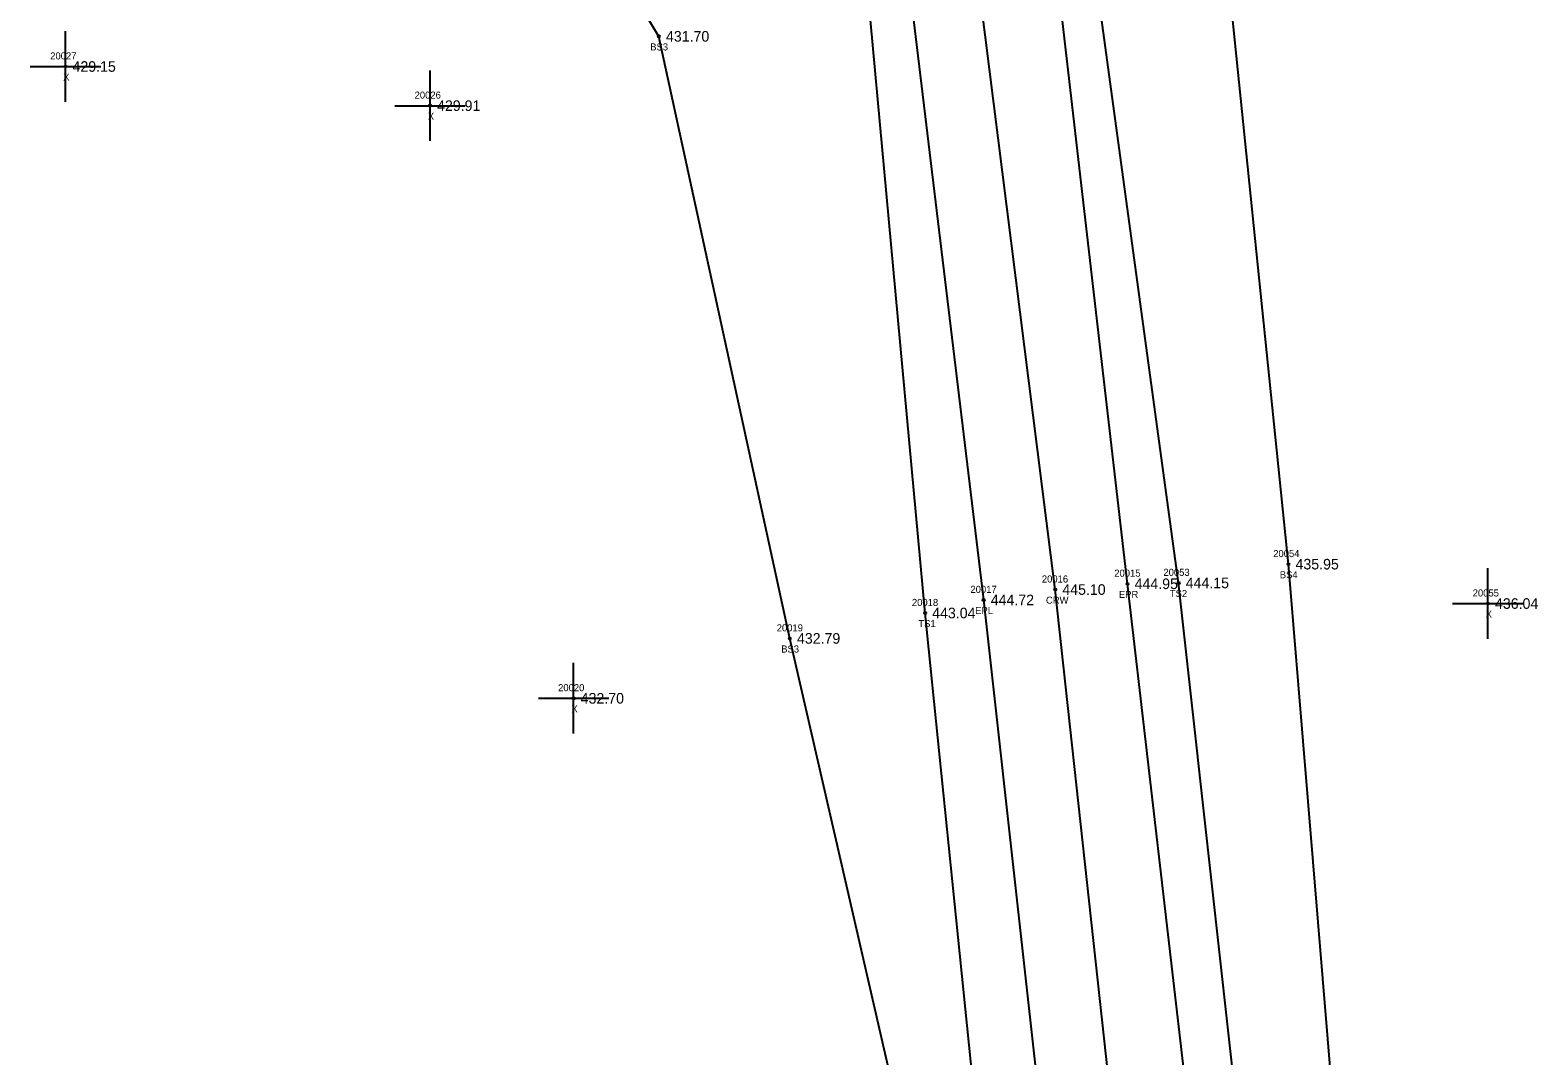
# Model space of a CAD drawing. Extents: x 1858461 to 1858936, y 1147060 to 1148183.
# Drawn here: x 1858580.6 to 1858794.2, y 1147205.1 to 1147350.4 of the extents above; entities that cross this region are included whole.
import ezdxf

# ---------------------------------------------------------------- set-up
doc = ezdxf.new("R2010")
doc.units = 0
for name, color, linetype in [('RD_DTM_BkLn1', 7, 'Continuous'), ('RD_DTM_BkLn2', 7, 'Continuous'), ('RD_DTM_BkLn_txCode', 7, 'Continuous'), ('RD_EX_Misc', 7, 'Continuous'), ('RD_EX_Misc_txCode', 7, 'Continuous'), ('RD_EX_Road', 7, 'Continuous'), ('RD_EX_Road_txCode', 7, 'Continuous'), ('RD_EX_TX_Misc_ELEV', 7, 'Continuous'), ('RD_EX_TX_Road_ELEV', 7, 'Continuous'), ('RD_HC_Survey_ELEV', 7, 'Continuous'), ('RD_HC_Survey_txCode', 7, 'Continuous'), ('RD_SMD_Locator', 7, 'Continuous')]:
    doc.layers.add(name, color=color, linetype=linetype)

msp = doc.modelspace()

# ---------------------------------------------------------------- linework, layer by layer
at = {"layer": 'RD_DTM_BkLn1'}
msp.add_lwpolyline([(1858749.22, 1147073.22), (1858736.71, 1147171.73), (1858725.84, 1147271.15), (1858713.42, 1147369.59), (1858701.55, 1147469.39), (1858689.32, 1147570.79)], dxfattribs=at)
at = {"layer": 'RD_DTM_BkLn2'}
for points in [[(1858771.94, 1147076.95), (1858767.25, 1147173.88), (1858758.88, 1147274.75), (1858748.81, 1147373.06), (1858739.11, 1147481.44), (1858733.31, 1147573.26), (1858722.73, 1147591.49), (1858706.35, 1147596.83)], [(1858714.74, 1147067.6), (1858710.56, 1147167.02), (1858688.24, 1147264.23), (1858669.68, 1147349.51), (1858651.77, 1147379.27), (1858656.32, 1147386.54), (1858661.34, 1147469.11), (1858657.4, 1147555.08), (1858671.87, 1147580.02)], [(1858771.94, 1147076.95), (1858754.29, 1147172.99), (1858743.32, 1147272.09), (1858729.94, 1147370.14), (1858717.88, 1147470.38), (1858711.02, 1147558.86), (1858710.29, 1147569.23), (1858703.02, 1147572.69)], [(1858727.7, 1147071.22), (1858717.51, 1147168.6), (1858707.4, 1147267.83), (1858698.1, 1147368.78), (1858685.2, 1147467.75), (1858675.58, 1147560.05), (1858676.79, 1147568.87)]]:
    msp.add_lwpolyline(points, dxfattribs=at)
at = {"layer": 'RD_EX_Misc'}
for p, q in [((1858585.6, 1147340.24), (1858585.6, 1147350.24)), ((1858580.6, 1147345.24), (1858590.6, 1147345.24)), ((1858637.25, 1147334.69), (1858637.25, 1147344.69)), ((1858632.25, 1147339.69), (1858642.25, 1147339.69)), ((1858787.14, 1147264.17), (1858787.14, 1147274.17)), ((1858782.14, 1147269.17), (1858792.14, 1147269.17)), ((1858657.6, 1147250.75), (1858657.6, 1147260.75)), ((1858652.6, 1147255.75), (1858662.6, 1147255.75))]:
    msp.add_line(p, q, dxfattribs=at)
at = {"layer": 'RD_EX_Road'}
for points in [[(1858760.33, 1147074.17), (1858747.61, 1147172.63), (1858736.08, 1147271.97), (1858724.51, 1147372.2), (1858712.86, 1147470.38), (1858700.06, 1147571.96), (1858689.32, 1147570.79)], [(1858739.58, 1147072.32), (1858726.74, 1147170.58), (1858715.7, 1147269.68), (1858703.76, 1147368.69), (1858691.45, 1147468.11), (1858680.5, 1147569.65), (1858689.32, 1147570.79)]]:
    msp.add_lwpolyline(points, dxfattribs=at)
at = {"layer": 'RD_SMD_Locator'}
for centre in [(1858669.68, 1147349.51), (1858585.6, 1147345.24), (1858637.25, 1147339.69), (1858758.88, 1147274.75), (1858725.84, 1147271.15), (1858736.08, 1147271.97), (1858743.32, 1147272.09), (1858715.7, 1147269.68), (1858787.14, 1147269.17), (1858707.4, 1147267.83), (1858688.24, 1147264.23), (1858657.6, 1147255.75)]:
    msp.add_circle(centre, 0.15, dxfattribs=at)

# ---------------------------------------------------------------- texts
at = {"layer": 'RD_DTM_BkLn_txCode'}
for s, p in [('BS3', (1858668.45, 1147347.51)), ('20054', (1858756.72, 1147275.75)), ('20053', (1858741.16, 1147273.09)), ('BS4', (1858757.65, 1147272.75)), ('TS2', (1858742.07, 1147270.09)), ('20018', (1858705.53, 1147268.83)), ('20019', (1858686.37, 1147265.23)), ('TS1', (1858706.44, 1147265.83)), ('BS3', (1858687.01, 1147262.23))]:
    msp.add_text(s, height=1, dxfattribs=at).set_placement(p)
at = {"layer": 'RD_EX_Misc_txCode'}
for s, p in [('20027', (1858583.44, 1147346.24)), ('X', (1858585.28, 1147343.24)), ('20026', (1858635.07, 1147340.69)), ('X', (1858636.94, 1147337.69)), ('20055', (1858784.98, 1147270.17)), ('X', (1858786.82, 1147267.17)), ('20020', (1858655.4, 1147256.75)), ('X', (1858657.28, 1147253.75))]:
    msp.add_text(s, height=1, dxfattribs=at).set_placement(p)
at = {"layer": 'RD_EX_Road_txCode'}
for s, p in [('20015', (1858734.2, 1147272.97)), ('20017', (1858713.82, 1147270.68)), ('EPR', (1858734.85, 1147269.97)), ('EPL', (1858714.49, 1147267.68))]:
    msp.add_text(s, height=1, dxfattribs=at).set_placement(p)
at = {"layer": 'RD_EX_TX_Misc_ELEV'}
for s, p in [('431.70', (1858670.68, 1147348.76)), ('429.15', (1858586.6, 1147344.49)), ('429.91', (1858638.25, 1147338.94)), ('435.95', (1858759.88, 1147274)), ('444.15', (1858744.32, 1147271.34)), ('443.04', (1858708.4, 1147267.08)), ('436.04', (1858788.14, 1147268.42)), ('432.79', (1858689.24, 1147263.48)), ('432.70', (1858658.6, 1147255))]:
    msp.add_text(s, height=1.5, dxfattribs=at).set_placement(p)
at = {"layer": 'RD_EX_TX_Road_ELEV'}
for s, p in [('444.95', (1858737.08, 1147271.22)), ('444.72', (1858716.7, 1147268.93))]:
    msp.add_text(s, height=1.5, dxfattribs=at).set_placement(p)
at = {"layer": 'RD_HC_Survey_ELEV'}
msp.add_text('445.10', height=1.5, dxfattribs=at).set_placement((1858726.84, 1147270.4))
at = {"layer": 'RD_HC_Survey_txCode'}
for s, p in [('20016', (1858723.94, 1147272.15)), ('CRW', (1858724.52, 1147269.15))]:
    msp.add_text(s, height=1, dxfattribs=at).set_placement(p)

doc.saveas('drawing.dxf')
